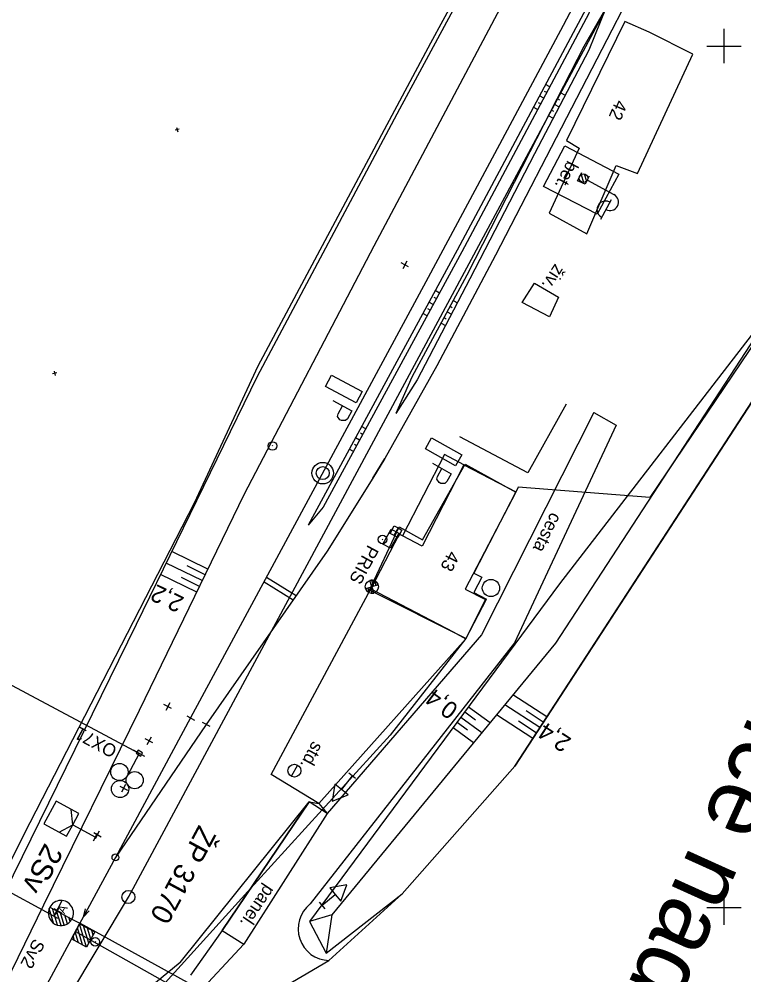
# Model space of a CAD drawing. Extents: x -795094 to -794639, y -1135368 to -1134681.
# Drawn here: x -794881.8 to -794797.7, y -1135007.8 to -1134896.9 of the extents above; entities that cross this region are included whole.
import ezdxf

# ---------------------------------------------------------------- set-up
doc = ezdxf.new("R2010")
doc.units = 0
for name, color, linetype in [('0381KM005-009P - Vrstva 1', 7, 'Continuous'), ('0381KM005-009P - Vrstva 12', 7, 'Continuous'), ('0381KM005-009P - Vrstva 16', 7, 'Continuous'), ('0381KM005-009P - Vrstva 17', 7, 'Continuous'), ('0381KM005-009P - Vrstva 2', 7, 'Continuous'), ('0381KM005-009P - Vrstva 23', 7, 'Continuous'), ('0381KM005-009P - Vrstva 25', 7, 'Continuous'), ('0381KM005-009P - Vrstva 28', 7, 'Continuous'), ('0381KM005-009P - Vrstva 3', 7, 'Continuous'), ('0381KM005-009P - Vrstva 33', 7, 'Continuous'), ('0381KM005-009P - Vrstva 4', 7, 'Continuous'), ('0381KM005-009P - Vrstva 41', 7, 'Continuous'), ('0381KM005-009P - Vrstva 43', 7, 'Continuous'), ('0381KM005-009P - Vrstva 48', 7, 'Continuous'), ('0381KM005-009P - Vrstva 49', 7, 'Continuous'), ('0381KM005-009P - Vrstva 51', 7, 'Continuous'), ('0381KM005-009P - Vrstva 55', 7, 'Continuous'), ('0381KM005-009P - Vrstva 57', 7, 'Continuous'), ('0381KM005-009P - Vrstva 6', 7, 'Continuous'), ('0381KM005-009P - Vrstva 7', 7, 'Continuous'), ('0381KM005-009P - Vrstva 8', 7, 'Continuous'), ('hran DP - hran DP', 7, 'Continuous'), ('krizky_1000 - Vrstva 1', 7, 'Continuous'), ('vyt_sit - ohrožené', 7, 'Continuous'), ('vyt_sit - polygon', 7, 'Continuous'), ('vyt_sit - stávající', 7, 'Continuous')]:
    doc.layers.add(name, color=color, linetype=linetype)

msp = doc.modelspace()

# ---------------------------------------------------------------- linework, layer by layer
at = {"layer": '0381KM005-009P - Vrstva 1'}
for points in [[(-794788.58, -1134840.28), (-794803.19, -1134868.16), (-794810.38, -1134881.86), (-794818.66, -1134897.6), (-794826.62, -1134912.5), (-794834.33, -1134926.85), (-794861.92, -1134977.99)], [(-794786.96, -1134841.36), (-794793.84, -1134858.32), (-794800.91, -1134874.12), (-794807.73, -1134887.87), (-794826.52, -1134924.29), (-794833.34, -1134937.13), (-794839.37, -1134947.86), (-794840.75, -1134950.16), (-794846.08, -1134958.61), (-794850.88, -1134965.55), (-794860.1, -1134978.74)], [(-794861.92, -1134977.99), (-794870.64, -1134994.17), (-794874.38, -1135001.11), (-794874.77, -1135001.82)], [(-794860.1, -1134978.74), (-794870.64, -1134994.17), (-794874.38, -1135001.11), (-794874.77, -1135001.82)], [(-794874.77, -1135001.82), (-794875.27, -1135002.76), (-794882.94, -1135016.95), (-794888.88, -1135027.93)]]:
    msp.add_lwpolyline(points, dxfattribs=at)
at = {"layer": '0381KM005-009P - Vrstva 12'}
for p, q in [((-794868.25, -1134982.09), (-794868.25, -1134982.09)), ((-794867.71, -1134982.41), (-794867.71, -1134982.41)), ((-794867.49, -1134982.03), (-794867.49, -1134982.04))]:
    msp.add_line(p, q, dxfattribs=at)
msp.add_lwpolyline([(-794868.02, -1134981.72), (-794868.25, -1134982.09), (-794867.71, -1134982.41), (-794867.49, -1134982.03), (-794868.02, -1134981.72), (-794868.02, -1134981.73), (-794868.25, -1134982.09), (-794867.71, -1134982.41), (-794867.49, -1134982.04), (-794868.02, -1134981.73)], dxfattribs=at)
at = {"layer": '0381KM005-009P - Vrstva 16'}
for p, q in [((-794848.16, -1134987.72), (-794858.24, -1135002.66)), ((-794846.07, -1134989.06), (-794848.16, -1134987.72)), ((-794848.16, -1134987.72), (-794847.03, -1134987.93)), ((-794847.03, -1134987.93), (-794846.07, -1134989.06)), ((-794858.24, -1135002.66), (-794855.73, -1135004.24))]:
    msp.add_line(p, q, dxfattribs=at)
for points in [[(-794818.48, -1134911.58), (-794812.2, -1134914.87), (-794814.71, -1134919.51), (-794820.93, -1134916.29), (-794818.48, -1134911.58)], [(-794822, -1134927.54), (-794819.21, -1134929.13), (-794820.25, -1134931.43), (-794823.42, -1134929.75), (-794822, -1134927.54)]]:
    msp.add_lwpolyline(points, dxfattribs=at)
at = {"layer": '0381KM005-009P - Vrstva 17'}
for points in [[(-794815.66, -1134915.11), (-794816.11, -1134916.05), (-794816.99, -1134915.63), (-794816.5, -1134914.67)], [(-794818.32, -1134941.56), (-794822.76, -1134949.53), (-794830.66, -1134945.36)], [(-794829.98, -1134968.8), (-794847.03, -1134987.93), (-794852.58, -1134984.56), (-794841.01, -1134963.01)]]:
    msp.add_lwpolyline(points, dxfattribs=at)
at = {"layer": '0381KM005-009P - Vrstva 2'}
for p, q in [((-794862.36, -1134977.76), (-794861.48, -1134978.23)), ((-794859.66, -1134978.98), (-794860.54, -1134978.5)), ((-794860.1, -1134978.74), (-794870.64, -1134994.17)), ((-794877.83, -1135001.81), (-794878.34, -1135000.12)), ((-794878.26, -1134999.94), (-794875.69, -1135001.33)), ((-794878.26, -1134999.94), (-794878.26, -1134999.94)), ((-794877.37, -1135002.04), (-794877.95, -1135000.11)), ((-794876.96, -1135002.09), (-794877.47, -1135000.36)), ((-794876.58, -1135002.04), (-794877, -1135000.62)), ((-794876.22, -1135001.89), (-794876.53, -1135000.87)), ((-794875.9, -1135001.63), (-794876.05, -1135001.13)), ((-794875.69, -1135001.33), (-794874.77, -1135001.82)), ((-794830.92, -1135025.88), (-794874.77, -1135001.82))]:
    msp.add_line(p, q, dxfattribs=at)
for points in [[(-794861.92, -1134977.99), (-794870.64, -1134994.17), (-794874.38, -1135001.11), (-794874.77, -1135001.82)], [(-794874.15, -1135000.14), (-794874.38, -1135001.11), (-794873.69, -1135000.38)]]:
    msp.add_lwpolyline(points, dxfattribs=at)
msp.add_circle((-794870.64, -1134994.17), 0.4, dxfattribs=at)
for start, end in [(331.5973, 152.0668), (151.6868, 331.6477)]:
    msp.add_arc((-794876.97, -1135000.63), 1.46, start, end, dxfattribs=at)
at = {"layer": '0381KM005-009P - Vrstva 23'}
for p, q in [((-794832.46, -1134947.42), (-794837.31, -1134956.85)), ((-794830.18, -1134948.61), (-794832.46, -1134947.42)), ((-794830.18, -1134948.61), (-794824.17, -1134951.75)), ((-794837.72, -1134956.67), (-794841.01, -1134963.01)), ((-794837.31, -1134956.85), (-794837.72, -1134956.67)), ((-794828.11, -1134961.66), (-794829.04, -1134963.44)), ((-794841.01, -1134963.01), (-794831.42, -1134967.99)), ((-794829.04, -1134963.44), (-794827.57, -1134964.21)), ((-794829.98, -1134968.8), (-794827.57, -1134964.21)), ((-794831.42, -1134967.99), (-794829.98, -1134968.8))]:
    msp.add_line(p, q, dxfattribs=at)
for points in [[(-794830.18, -1134948.61), (-794835.02, -1134958.03), (-794837.31, -1134956.85)], [(-794824.17, -1134951.75), (-794829.02, -1134961.18), (-794828.11, -1134961.66)]]:
    msp.add_lwpolyline(points, dxfattribs=at)
at = {"layer": '0381KM005-009P - Vrstva 25'}
for p, q in [((-794816.57, -1134914.92), (-794816.3, -1134915.84)), ((-794816.21, -1134914.85), (-794815.95, -1134915.69)), ((-794815.86, -1134915.58), (-794812.78, -1134917.23)), ((-794813.11, -1134917.85), (-794814.34, -1134920.14))]:
    msp.add_line(p, q, dxfattribs=at)
msp.add_lwpolyline([(-794838.64, -1134956.06), (-794837.76, -1134956.53), (-794838.71, -1134958.29), (-794839.59, -1134957.82), (-794838.64, -1134956.06)], dxfattribs=at)
msp.add_circle((-794816.3, -1134915.34), 0.5, dxfattribs=at)
for centre, start, end in [((-794813.25, -1134918.11), 241.7362, 61.7362), ((-794813.74, -1134918.99), 61.0336, 242.4387)]:
    msp.add_arc(centre, 1, start, end, dxfattribs=at)
at = {"layer": '0381KM005-009P - Vrstva 28'}
for p, q in [((-794839.66, -1134957.33), (-794839.61, -1134957.24)), ((-794872.95, -1135003.92), (-794873, -1135004.01))]:
    msp.add_line(p, q, dxfattribs=at)
for centre in [(-794839.64, -1134957.28), (-794872.98, -1135003.96)]:
    msp.add_circle(centre, 0.5, dxfattribs=at)
at = {"layer": '0381KM005-009P - Vrstva 3'}
for p, q in [((-794873.99, -1135004.59), (-794874.8, -1135001.88)), ((-794874.92, -1135004.09), (-794875.3, -1135002.82)), ((-794874.45, -1135004.34), (-794875.05, -1135002.35)), ((-794873.74, -1135004.12), (-794874.33, -1135002.13)), ((-794873.48, -1135003.66), (-794873.87, -1135002.39)), ((-794873.23, -1135003.19), (-794873.4, -1135002.64)), ((-794875.39, -1135003.84), (-794875.55, -1135003.28))]:
    msp.add_line(p, q, dxfattribs=at)
msp.add_lwpolyline([(-794875.75, -1135003.64), (-794874.8, -1135001.88), (-794873.04, -1135002.83), (-794873.99, -1135004.59)], close=True, dxfattribs=at)
msp.add_lwpolyline([(-794875.27, -1135002.76), (-794845.8, -1135019.38), (-794847.67, -1135022.54), (-794833.28, -1135030.23)], dxfattribs=at)
at = {"layer": '0381KM005-009P - Vrstva 33'}
for points in [[(-794842, -1134940.1), (-794842.71, -1134941.41), (-794846.26, -1134939.5), (-794845.55, -1134938.19)], [(-794830.42, -1134947.43), (-794831.15, -1134948.73), (-794834.66, -1134946.76), (-794833.94, -1134945.46)]]:
    msp.add_lwpolyline(points, close=True, dxfattribs=at)
for points in [[(-794845.4, -1134941.14), (-794843.2, -1134942.34)], [(-794844.78, -1134942.67), (-794844.29, -1134941.75)], [(-794843.69, -1134943.25), (-794843.93, -1134943.48), (-794844.4, -1134943.48), (-794844.59, -1134943.38), (-794844.85, -1134942.99), (-794844.78, -1134942.67)], [(-794843.2, -1134942.34), (-794843.69, -1134943.25)], [(-794833.84, -1134948.42), (-794831.66, -1134949.65)], [(-794833.25, -1134949.95), (-794832.74, -1134949.04)], [(-794831.66, -1134949.65), (-794832.17, -1134950.56)], [(-794832.17, -1134950.56), (-794832.41, -1134950.78), (-794832.88, -1134950.77), (-794833.07, -1134950.66), (-794833.32, -1134950.27), (-794833.25, -1134949.95)]]:
    msp.add_lwpolyline(points, dxfattribs=at)
at = {"layer": '0381KM005-009P - Vrstva 4'}
msp.add_line((-794840.75, -1134950.16), (-794839.37, -1134947.86), dxfattribs=at)
at = {"layer": '0381KM005-009P - Vrstva 41'}
msp.add_line((-794849.52, -1134983.45), (-794850.23, -1134984.77), dxfattribs=at)
msp.add_circle((-794849.87, -1134984.11), 0.752, dxfattribs=at)
at = {"layer": '0381KM005-009P - Vrstva 43'}
msp.add_lwpolyline([(-794837.83, -1134955.94), (-794837.39, -1134956.18), (-794837.87, -1134957.06), (-794838.75, -1134956.58), (-794838.27, -1134955.7), (-794837.83, -1134955.94), (-794838.31, -1134956.82)], dxfattribs=at)
msp.add_circle((-794827.05, -1134962.91), 1, dxfattribs=at)
at = {"layer": '0381KM005-009P - Vrstva 48'}
for p, q in [((-794820.57, -1134905.4), (-794820.82, -1134905.26)), ((-794820.21, -1134904.73), (-794820.73, -1134904.46)), ((-794820.92, -1134906.06), (-794821.43, -1134905.78)), ((-794819.37, -1134906.08), (-794819.08, -1134906.23)), ((-794819.03, -1134905.41), (-794818.44, -1134905.72)), ((-794821.63, -1134907.38), (-794822.14, -1134907.11)), ((-794821.27, -1134906.72), (-794821.53, -1134906.58)), ((-794820.06, -1134907.42), (-794819.77, -1134907.56)), ((-794819.71, -1134906.75), (-794819.13, -1134907.05)), ((-794820.4, -1134908.08), (-794819.83, -1134908.38)), ((-794833.03, -1134928.67), (-794833.54, -1134928.39)), ((-794833.74, -1134929.98), (-794834.26, -1134929.71)), ((-794833.39, -1134929.32), (-794833.64, -1134929.19)), ((-794831.42, -1134929.54), (-794830.95, -1134929.79)), ((-794834.1, -1134930.64), (-794834.36, -1134930.51)), ((-794832.13, -1134930.86), (-794831.64, -1134931.12)), ((-794831.78, -1134930.2), (-794831.54, -1134930.33)), ((-794834.46, -1134931.3), (-794834.97, -1134931.03)), ((-794832.49, -1134931.52), (-794832.24, -1134931.65)), ((-794832.84, -1134932.18), (-794832.34, -1134932.45)), ((-794841.59, -1134944.42), (-794842.07, -1134944.15)), ((-794841.95, -1134945.08), (-794842.19, -1134944.95)), ((-794842.66, -1134946.4), (-794842.9, -1134946.26)), ((-794842.3, -1134945.74), (-794842.79, -1134945.47)), ((-794843.02, -1134947.05), (-794843.5, -1134946.79)), ((-794859.9, -1134960.7), (-794864.09, -1134958.66)), ((-794860.56, -1134962.05), (-794864.75, -1134960.01)), ((-794860.23, -1134961.37), (-794862.32, -1134960.35)), ((-794861.21, -1134963.4), (-794865.41, -1134961.35)), ((-794860.88, -1134962.72), (-794862.98, -1134961.7)), ((-794820.56, -1134977.84), (-794824.49, -1134975.29)), ((-794830.09, -1134977.28), (-794828.86, -1134978.19)), ((-794829.64, -1134976.68), (-794827.15, -1134978.52)), ((-794821.38, -1134979.1), (-794825.45, -1134976.45)), ((-794820.97, -1134978.47), (-794822.97, -1134977.17)), ((-794830.98, -1134978.49), (-794829.78, -1134979.37)), ((-794830.53, -1134977.88), (-794828.11, -1134979.68)), ((-794822.2, -1134980.36), (-794826.41, -1134977.62)), ((-794821.79, -1134979.73), (-794823.86, -1134978.38)), ((-794831.42, -1134979.09), (-794829.06, -1134980.84))]:
    msp.add_line(p, q, dxfattribs=at)
at = {"layer": '0381KM005-009P - Vrstva 49'}
for p, q in [((-794799.26, -1134845.15), (-794840.65, -1134923.24)), ((-794824.73, -1134883.39), (-794837.68, -1134907.33)), ((-794837.68, -1134907.33), (-794854.18, -1134938.37)), ((-794863.23, -1134909.63), (-794863.7, -1134909.77)), ((-794863.54, -1134909.46), (-794863.39, -1134909.94)), ((-794840.65, -1134923.24), (-794855.69, -1134952.03)), ((-794792.99, -1134928.57), (-794819.56, -1134969.3)), ((-794792.99, -1134928.57), (-794819.08, -1134962.42)), ((-794790.5, -1134931.65), (-794824.29, -1134983.58)), ((-794877.46, -1134937.92), (-794877.93, -1134938.06)), ((-794877.77, -1134937.75), (-794877.62, -1134938.23)), ((-794854.18, -1134938.37), (-794868.24, -1134967.15)), ((-794855.69, -1134952.03), (-794867.89, -1134977.13)), ((-794819.08, -1134962.42), (-794848.1, -1135001.61)), ((-794868.24, -1134967.15), (-794883.51, -1134998.27)), ((-794819.56, -1134969.3), (-794845.52, -1135000.83)), ((-794867.89, -1134977.13), (-794879, -1134999.7)), ((-794837.37, -1134998.39), (-794824.29, -1134983.58)), ((-794863.12, -1135006.37), (-794848.16, -1134987.72)), ((-794858.24, -1135002.66), (-794848.16, -1134987.72)), ((-794846.17, -1135005.29), (-794837.37, -1134998.39)), ((-794879, -1134999.7), (-794890.34, -1135022.91)), ((-794845.52, -1135000.83), (-794848.1, -1135001.61)), ((-794848.1, -1135001.61), (-794846.17, -1135005.29)), ((-794845.52, -1135000.83), (-794846.17, -1135005.29)), ((-794858.24, -1135002.66), (-794861.94, -1135007.83)), ((-794863.12, -1135006.37), (-794872.47, -1135014.02))]:
    msp.add_line(p, q, dxfattribs=at)
for points in [[(-794815.37, -1134894.44), (-794815.67, -1134896.21), (-794830.44, -1134923.9), (-794846.52, -1134953.51), (-794848.28, -1134955.61)], [(-794815.37, -1134894.44), (-794830.99, -1134923.68), (-794848.28, -1134955.61)], [(-794813.73, -1134895.61), (-794815.7, -1134900.49), (-794822, -1134912.52), (-794829.49, -1134927.01), (-794835.62, -1134938.73), (-794838.1, -1134942.66)], [(-794813.73, -1134895.61), (-794816.27, -1134900.06), (-794822.55, -1134912.27), (-794829.83, -1134926.6), (-794836.24, -1134938.45), (-794838.1, -1134942.66)]]:
    msp.add_lwpolyline(points, dxfattribs=at)
at = {"layer": '0381KM005-009P - Vrstva 51'}
for p, q in [((-794815.11, -1134942.54), (-794828.15, -1134968.34)), ((-794815.11, -1134942.54), (-794812.52, -1134944)), ((-794812.52, -1134944), (-794824.3, -1134969.27)), ((-794828.15, -1134968.34), (-794846.07, -1134989.06)), ((-794824.3, -1134969.27), (-794848.05, -1134999.57)), ((-794842.77, -1134985.01), (-794843.56, -1134984.4)), ((-794846.07, -1134989.06), (-794855.73, -1135004.24)), ((-794846.99, -1134999.36), (-794846.35, -1135000.13)), ((-794855.73, -1135004.24), (-794871.74, -1135021.34))]:
    msp.add_line(p, q, dxfattribs=at)
for points in [[(-794871.74, -1135021.34), (-794845.86, -1135006.13), (-794837.37, -1134998.39), (-794824.29, -1134983.58), (-794790.5, -1134931.65), (-794766.19, -1134894.56)], [(-794843.16, -1134984.71), (-794844.39, -1134986.28), (-794845.18, -1134985.67), (-794845.47, -1134987.66), (-794843.61, -1134986.9), (-794844.39, -1134986.28)], [(-794846.67, -1134999.74), (-794845.13, -1134998.47), (-794844.49, -1134999.24), (-794843.78, -1134997.35), (-794845.77, -1134997.7), (-794845.13, -1134998.47)]]:
    msp.add_lwpolyline(points, dxfattribs=at)
msp.add_ellipse((-794845.74, -1135002.44), major_axis=(-2.17, -3.01), ratio=0.990529, start_param=4.446216, end_param=6.879975, dxfattribs=at)
at = {"layer": '0381KM005-009P - Vrstva 55'}
for points in [[(-794815.9, -1134921.79), (-794812.5, -1134913.85), (-794810.05, -1134914.8), (-794803.6, -1134900.93), (-794808.67, -1134898.39), (-794811.52, -1134897.15), (-794818.27, -1134910.96), (-794816.8, -1134911.86), (-794820.3, -1134919.39), (-794815.9, -1134921.79)], [(-794829.96, -1134968.76), (-794841.15, -1134963.17), (-794837.72, -1134955.82), (-794835, -1134957.3), (-794830.05, -1134948.55), (-794824.17, -1134951.78), (-794830.03, -1134963.03), (-794827.67, -1134964.22), (-794829.96, -1134968.76)]]:
    msp.add_lwpolyline(points, dxfattribs=at)
at = {"layer": '0381KM005-009P - Vrstva 6'}
for p, q in [((-794877.8, -1135000.98), (-794918.76, -1134978.92)), ((-794876.86, -1134999.23), (-794877.8, -1135000.98)), ((-794878.24, -1135000.74), (-794877.36, -1135001.21))]:
    msp.add_line(p, q, dxfattribs=at)
at = {"layer": '0381KM005-009P - Vrstva 7'}
for p, q in [((-794836.61, -1134925.64), (-794837.49, -1134925.16)), ((-794836.81, -1134924.96), (-794837.29, -1134925.84)), ((-794852.4, -1134946.37), (-794852.45, -1134946.46)), ((-794853.11, -1134961.66), (-794849.65, -1134963.78)), ((-794853.39, -1134962.19), (-794849.99, -1134964.27)), ((-794864.34, -1134976.22), (-794864.81, -1134977.11)), ((-794864.13, -1134976.9), (-794865.02, -1134976.43)), ((-794866.3, -1134980.89), (-794867.18, -1134980.42)), ((-794866.51, -1134980.21), (-794866.98, -1134981.09)), ((-794870.12, -1134985.89), (-794869.24, -1134986.37)), ((-794869.91, -1134986.57), (-794869.44, -1134985.69)), ((-794875.6, -1134990.4), (-794872.96, -1134991.82)), ((-794873.2, -1134992.26), (-794872.72, -1134991.38)), ((-794873.16, -1134991.3), (-794872.28, -1134991.78)), ((-794872.95, -1134991.98), (-794872.48, -1134991.1)), ((-794877.79, -1135000.12), (-794876.91, -1135000.59)), ((-794877.59, -1135000.8), (-794877.12, -1134999.92))]:
    msp.add_line(p, q, dxfattribs=at)
for points in [[(-794875.6, -1134990.4), (-794874.89, -1134989.08), (-794877.53, -1134987.65), (-794878.95, -1134990.29), (-794876.31, -1134991.72), (-794875.6, -1134990.4)], [(-794877.19, -1134991.24), (-794875.6, -1134990.4), (-794875.77, -1134988.6)]]:
    msp.add_lwpolyline(points, dxfattribs=at)
for centre, radius in [((-794852.42, -1134946.42), 0.5), ((-794846.58, -1134949.57), 1.25), ((-794846.58, -1134949.57), 0.752)]:
    msp.add_circle(centre, radius, dxfattribs=at)
at = {"layer": '0381KM005-009P - Vrstva 8'}
for p, q in [((-794867.87, -1134982.1), (-794910.23, -1134959.53)), ((-794867.21, -1134982.45), (-794868.53, -1134981.74)), ((-794867.87, -1134982.1), (-794869.29, -1134984.74))]:
    msp.add_line(p, q, dxfattribs=at)
for centre in [(-794870.18, -1134984.26), (-794870.1, -1134986.23), (-794868.41, -1134985.21)]:
    msp.add_circle(centre, 1, dxfattribs=at)
at = {"layer": 'hran DP - hran DP'}
for p, q in [((-794834.03, -1134899.62), (-794808.02, -1134851.51)), ((-794771.93, -1134898.11), (-794808.62, -1134952.39)), ((-794854.06, -1134937.12), (-794834.03, -1134899.62)), ((-794861.46, -1134953), (-794854.06, -1134937.12)), ((-794824.17, -1134951.78), (-794830.03, -1134963.03)), ((-794823.88, -1134951.22), (-794824.17, -1134951.78)), ((-794808.62, -1134952.39), (-794823.88, -1134951.22)), ((-794880.53, -1134990.11), (-794861.46, -1134953)), ((-794830.03, -1134963.03), (-794827.67, -1134964.22)), ((-794827.67, -1134964.22), (-794829.96, -1134968.76)), ((-794829.96, -1134968.76), (-794838.74, -1134979.98)), ((-794838.74, -1134979.98), (-794854.54, -1134997.31)), ((-794899.86, -1135028.32), (-794880.53, -1134990.11)), ((-794854.54, -1134997.31), (-794868.85, -1135013.13))]:
    msp.add_line(p, q, dxfattribs=at)
at = {"layer": 'krizky_1000 - Vrstva 1'}
for points in [[(-794800, -1134898), (-794800, -1134902)], [(-794802, -1134900), (-794798, -1134900)], [(-794800, -1134998), (-794800, -1135002)], [(-794802, -1135000), (-794798, -1135000)]]:
    msp.add_lwpolyline(points, dxfattribs=at)
at = {"layer": 'vyt_sit - ohrožené'}
msp.add_line((-794869.11, -1134998.72), (-794869.16, -1134998.81), dxfattribs=at)
msp.add_circle((-794869.14, -1134998.77), 0.756, dxfattribs=at)
at = {"layer": 'vyt_sit - polygon'}
for p, q in [((-794869.14, -1134998.77), (-794781.23, -1134835.33)), ((-794937.71, -1135113.7), (-794869.14, -1134998.77))]:
    msp.add_line(p, q, dxfattribs=at)
at = {"layer": 'vyt_sit - stávající'}
for p, q in [((-794841.61, -1134962.98), (-794840.88, -1134962.76)), ((-794841.36, -1134962.91), (-794841.2, -1134963.46)), ((-794840.88, -1134962.76), (-794841.1, -1134962.03)), ((-794841.08, -1134962.82), (-794840.87, -1134963.52)), ((-794840.9, -1134962), (-794840.69, -1134962.7)), ((-794840.15, -1134962.54), (-794840.88, -1134962.76)), ((-794840.88, -1134962.76), (-794840.66, -1134963.5)), ((-794840.57, -1134962.06), (-794840.4, -1134962.62))]:
    msp.add_line(p, q, dxfattribs=at)
msp.add_circle((-794840.88, -1134962.76), 0.764, dxfattribs=at)
for radius, start, end in [(0.765, 196.8737, 286.7672), (0.764, 16.1849, 106.5029)]:
    msp.add_arc((-794840.88, -1134962.76), radius, start, end, dxfattribs=at)

# ---------------------------------------------------------------- texts
at = {"layer": '0381KM005-009P - Vrstva 16'}
for s, rotation, p in [('bet.', 242.5643, (-794818.15, -1134913.2)), ('živ.', 237.1152, (-794819.6, -1134925.19)), ('panel.', 236.0023, (-794853.21, -1134997.21))]:
    msp.add_text(s, height=1.5, rotation=rotation, dxfattribs=at).set_placement(p)
at = {"layer": '0381KM005-009P - Vrstva 2'}
msp.add_text('2Sv', height=2.5, rotation=241.6673, dxfattribs=at).set_placement((-794878.81, -1134992.4))
at = {"layer": '0381KM005-009P - Vrstva 23'}
msp.add_text('žst. Strunkovice nad Volyňkou', height=8, rotation=245.663, dxfattribs=at).set_placement((-794771.54, -1134921.22))
at = {"layer": '0381KM005-009P - Vrstva 25'}
msp.add_text('PRIS', height=1.5, rotation=241.6619, dxfattribs=at).set_placement((-794841.32, -1134957.8))
at = {"layer": '0381KM005-009P - Vrstva 41'}
msp.add_text('std.', height=1.5, rotation=241.6619, dxfattribs=at).set_placement((-794847.72, -1134980.59))
at = {"layer": '0381KM005-009P - Vrstva 48'}
for s, rotation, p in [('2,2', 154.0658, (-794862.54, -1134964.05)), ('0,4', 143.4866, (-794830.7, -1134976.68)), ('2,4', 146.9481, (-794817.59, -1134980.43))]:
    msp.add_text(s, height=2, rotation=rotation, dxfattribs=at).set_placement(p)
at = {"layer": '0381KM005-009P - Vrstva 51'}
msp.add_text('cesta', height=1.5, rotation=243.1983, dxfattribs=at).set_placement((-794820.06, -1134954.02))
at = {"layer": '0381KM005-009P - Vrstva 57'}
for s, rotation, p in [('42', 246.6586, (-794812.52, -1134906.14)), ('43', 242.7802, (-794831.94, -1134958.49))]:
    msp.add_text(s, height=1.5, rotation=rotation, dxfattribs=at).set_placement(p)
at = {"layer": '0381KM005-009P - Vrstva 6'}
for s, height, rotation, p in [('  A ', 1, 61.6764, (-794876.92, -1135001.45)), ('Sv2', 1.5, 241.6764, (-794880.08, -1135003.5))]:
    msp.add_text(s, height=height, rotation=rotation, dxfattribs=at).set_placement(p)
at = {"layer": '0381KM005-009P - Vrstva 8'}
msp.add_text('OX71', height=1.5, rotation=151.6652, dxfattribs=at).set_placement((-794870.32, -1134981.38))
at = {"layer": 'vyt_sit - ohrožené'}
msp.add_text('ŽP 3170', height=2.4, rotation=241.6714, dxfattribs=at).set_placement((-794860.94, -1134990.31))

doc.saveas('drawing.dxf')
